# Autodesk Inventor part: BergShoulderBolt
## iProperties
Author: sbraun
Shininess: 70.0
PropertySet Name: _Private Model Information
Created: 2001-01
Part Number: BergShoulderBolt
Material: Stainless Steel, 416
Document SubType Name: Modeling
Designer: Ron Crain
Vendor: WM BERG
Control State: 0
Master: False
Checked Out: False
PropertySet Name: Design Tracking Control
Density: 7.84
Volumn: 2.8652506634014827
Area: 15.320499213466766
PropertySet Name: Model Information
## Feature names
1. shoulder size [Extrusion]
2. head [Extrusion]
3. shoulder neck [Extrusion]
4. hex size [Extrusion]
5. thread size [Extrusion]
6. thread neck [Extrusion]
7. Chamfer2
